(* Logix 5000 project; controller MVI69ADM vendor 1 type 14 code 65 rev 13.1; software revision 13.00 *)
// Sample Ladder for MVI69-ADM

TASK MainTask (continuous, watchdog 500 ms) : MainProgram

MODULES
   Controller : vendor 1 type 14 code 65 (CompactLogixL35Controller 0, rev 13.1)
      LocalENB : 1769-L35E Ethernet Port (CompactLogixL35Ethernet 1, Ethernet 192.168.0.149, rev 13.1)
      Local : CompactBus (CompactVirtualAdapter 3, rev 13.1, Output RPI 2 ms)
         MVI69 : 1769-MODULE (Compact 1, rev 1.1, Output RPI 2 ms)
END_MODULES

TYPE ADMModuleDef :
STRUCT
   ReadData : INT[600];
   WriteData : INT[600];
END_STRUCT
END_TYPE

VAR_GLOBAL   (* controller tags *)
   ADM : ADMModuleDef;
   Port2Count : INT := 2006;
   SendDataPort1 : BOOL;
   SendDataPort2 : BOOL;
   SerialCount : INT := 1;
END_VAR

PROGRAM MainProgram   (* routine attr 65 MainRoutine *)
VAR
   MCM : DINT;
END_VAR

ROUTINE MainRoutine   (* ladder *)
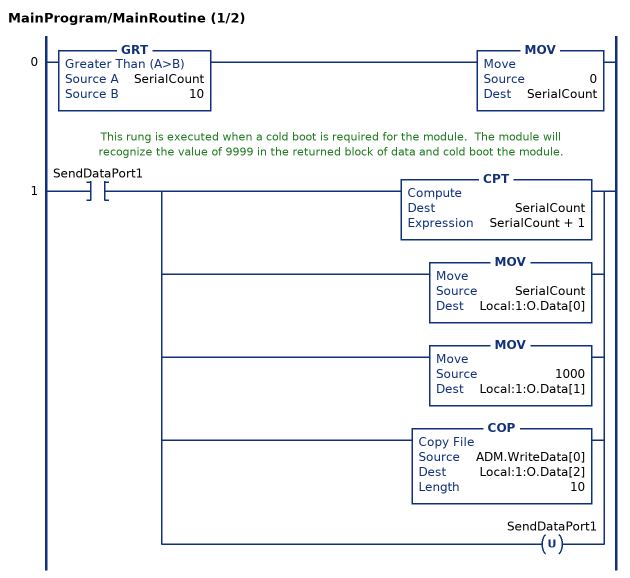
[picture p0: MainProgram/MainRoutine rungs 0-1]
   0: GRT(SerialCount,10)MOV(0,SerialCount);
   // This rung is executed when a cold boot is required for the module.  The module will recognize the value of 9999 in the returned block of data and cold boot the module.
   1: XIC(SendDataPort1)[CPT(SerialCount,SerialCount + 1) ,MOV(SerialCount,Local:1:O.Data[0]) ,MOV(1000,Local:1:O.Data[1]) ,COP(ADM.WriteData[0],Local:1:O.Data[2],10) ,OTU(SendDataPort1) ];
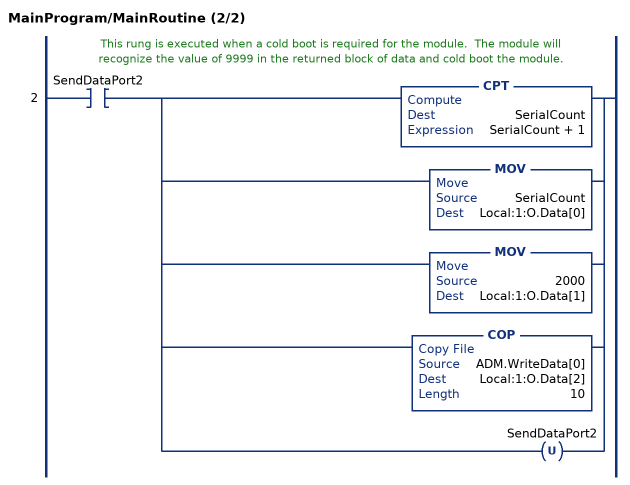
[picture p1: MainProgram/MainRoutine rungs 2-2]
   // This rung is executed when a cold boot is required for the module.  The module will recognize the value of 9999 in the returned block of data and cold boot the module.
   2: XIC(SendDataPort2)[CPT(SerialCount,SerialCount + 1) ,MOV(SerialCount,Local:1:O.Data[0]) ,MOV(2000,Local:1:O.Data[1]) ,COP(ADM.WriteData[0],Local:1:O.Data[2],10) ,OTU(SendDataPort2) ];
END_ROUTINE
END_PROGRAM
